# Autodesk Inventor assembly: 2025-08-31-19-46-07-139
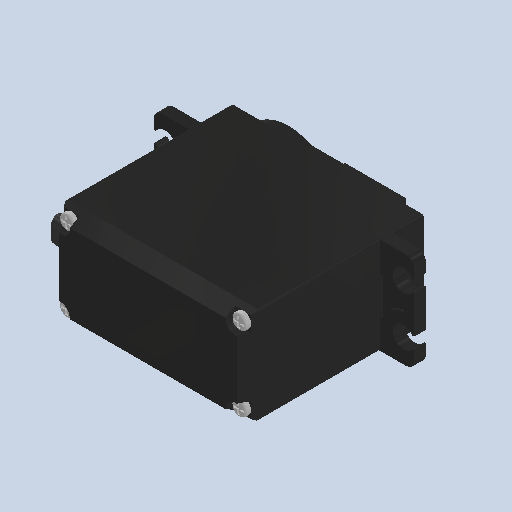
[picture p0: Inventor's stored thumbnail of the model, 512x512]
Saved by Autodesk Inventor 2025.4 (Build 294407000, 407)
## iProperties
Created: 2026-09
Part Number: 2025-08-31-19-46-07-139
Document SubType Name: Assembly
Designer: AdminForWorker
Title: Servo
Author: AdminForWorker
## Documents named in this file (5)
- c:\worker\convert-fusion-r05-cosv3\tmp\job-1\19\temp\files\ca3d996b-dda0-445d-8bee-12a194174ca8\Servo.iam
- c:\worker\convert-fusion-r05-cosv3\tmp\job-1\19\temp\files\ca3d996b-dda0-445d-8bee-12a194174ca8\com_top.iam
- c:\worker\convert-fusion-r05-cosv3\tmp\job-1\19\temp\files\ca3d996b-dda0-445d-8bee-12a194174ca8\com_but.ipt
- c:\worker\convert-fusion-r05-cosv3\tmp\job-1\19\temp\files\ca3d996b-dda0-445d-8bee-12a194174ca8\Gear.ipt
- c:\worker\convert-fusion-r05-cosv3\tmp\job-1\19\temp\files\ca3d996b-dda0-445d-8bee-12a194174ca8\bolts.ipt
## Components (4 placed, 4 different names)
1. com_top:1 [sub-assembly]
2. com_but:1
3. Gear:1
4. bolts:1
